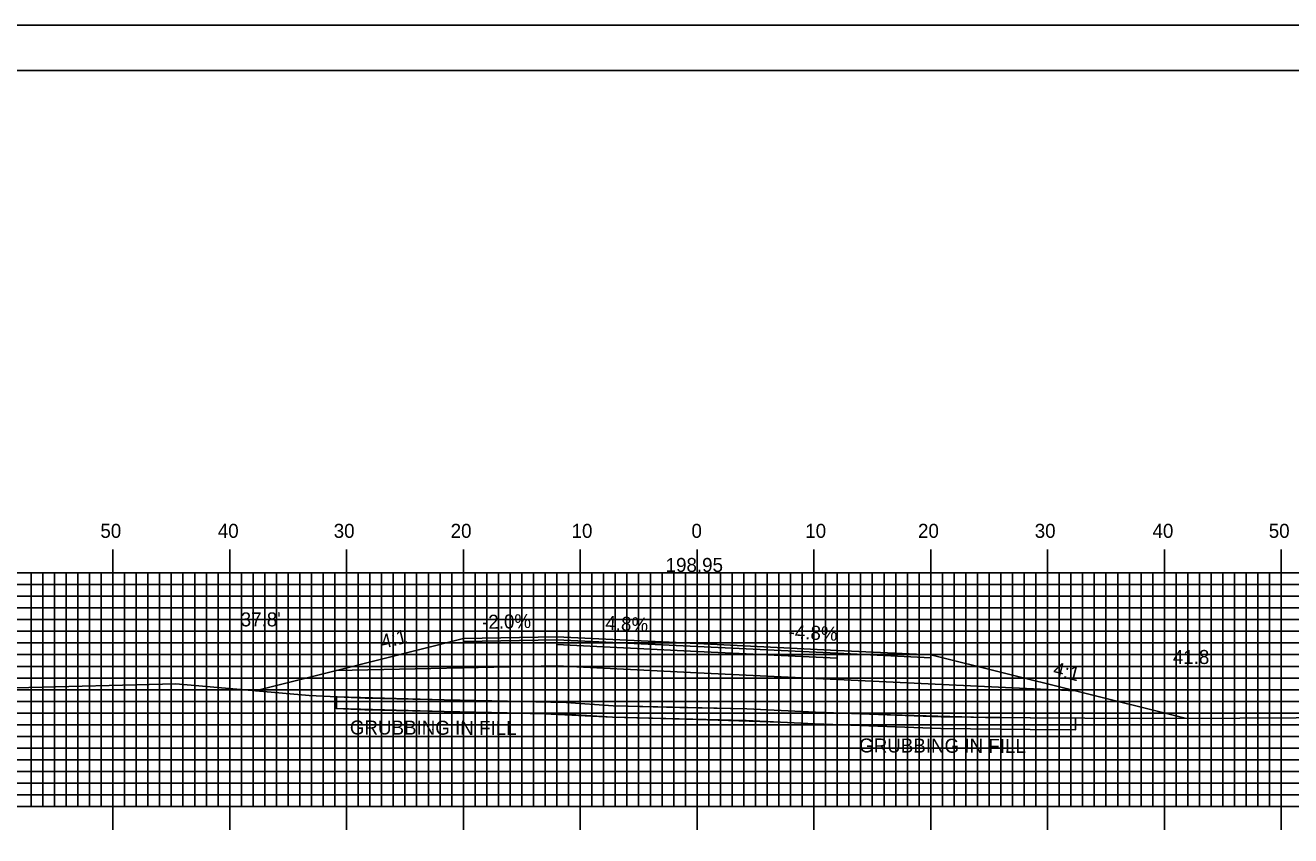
# Model space of a CAD drawing. Extents: x 1814128 to 1814471, y 442591 to 442811.
# Drawn here: x 1814236.5 to 1814344.8, y 442741.2 to 442810.5 of the extents above; entities that cross this region are included whole.
import ezdxf

# ---------------------------------------------------------------- set-up
doc = ezdxf.new("R2010")
doc.units = 0
for name, color, linetype in [('ANNOTATION', 7, 'Continuous'), ('BORDER', 7, 'Continuous'), ('D_Roadway_Centerline', 7, 'Continuous'), ('D_Roadway_Centerline_Text', 7, 'Continuous'), ('D_Roadway_Edge_Shoulder', 7, 'Continuous'), ('D_Roadway_Edge_TW', 7, 'Continuous'), ('D_Roadway_Pavement', 7, 'Continuous'), ('D_Roadway_SlopeLines', 7, 'Continuous'), ('D_Roadway_SubGrade', 7, 'Continuous'), ('D_Text_Standard', 7, 'Continuous'), ('GRUBBING IN FILL', 7, 'Continuous'), ('H_V ANNOTATION', 7, 'Continuous'), ('MAJOR', 7, 'Continuous'), ('MINOR', 7, 'Continuous'), ('PLOT BOUNDARY', 7, 'Continuous'), ('S_Roadway_Centerline', 7, 'Continuous')]:
    doc.layers.add(name, color=color, linetype=linetype)

msp = doc.modelspace()

# ---------------------------------------------------------------- linework, layer by layer
at = {"layer": 'BORDER'}
msp.add_lwpolyline([(1814144.39, 442596.67), (1814464.39, 442596.67), (1814464.39, 442806.67), (1814144.39, 442806.67)], close=True, dxfattribs=at)
at = {"layer": 'D_Roadway_Centerline'}
msp.add_lwpolyline([(1814256.17, 442753.58), (1814261.99, 442755.04), (1814263.12, 442755.32), (1814273.99, 442758.04), (1814281.99, 442758.2), (1814293.99, 442757.62), (1814305.99, 442757.04), (1814313.99, 442756.66), (1814326.37, 442753.57), (1814335.77, 442751.22)], dxfattribs=at)
at = {"layer": 'D_Roadway_Edge_Shoulder'}
for points in [[(1814281.99, 442758.2), (1814273.99, 442758.04), (1814273.99, 442757.79), (1814281.99, 442757.95)], [(1814305.99, 442757.04), (1814313.99, 442756.66), (1814313.99, 442756.41), (1814305.99, 442756.79)]]:
    msp.add_lwpolyline(points, close=True, dxfattribs=at)
at = {"layer": 'D_Roadway_Edge_TW'}
msp.add_lwpolyline([(1814281.99, 442757.95), (1814281.99, 442758.2), (1814293.99, 442757.62), (1814305.99, 442757.04), (1814305.99, 442756.79), (1814293.99, 442757.37)], close=True, dxfattribs=at)
at = {"layer": 'D_Roadway_Pavement'}
msp.add_lwpolyline([(1814281.99, 442757.53), (1814281.99, 442757.95), (1814293.99, 442757.37), (1814305.99, 442756.79), (1814305.99, 442756.38), (1814293.99, 442756.95)], close=True, dxfattribs=at)
at = {"layer": 'D_Roadway_SlopeLines'}
for points in [[(1814273.99, 442758.04), (1814263.12, 442755.32), (1814261.99, 442755.04), (1814256.17, 442753.58)], [(1814313.99, 442756.66), (1814326.37, 442753.57), (1814335.77, 442751.22)]]:
    msp.add_lwpolyline(points, dxfattribs=at)
at = {"layer": 'D_Roadway_SubGrade'}
msp.add_lwpolyline([(1814281.99, 442755.7), (1814263.12, 442755.32), (1814273.99, 442758.04), (1814273.99, 442757.79), (1814281.99, 442757.95), (1814293.99, 442757.37), (1814305.99, 442756.79), (1814313.99, 442756.41), (1814313.99, 442756.66), (1814326.37, 442753.57), (1814305.99, 442754.54), (1814293.99, 442755.12)], close=True, dxfattribs=at)
at = {"layer": 'GRUBBING IN FILL'}
for p, q in [((1814263.12, 442753.07), (1814263.12, 442752.06)), ((1814263.12, 442753.07), (1814263.12, 442752.06)), ((1814326.37, 442751.23), (1814326.37, 442750.23)), ((1814326.37, 442751.23), (1814326.37, 442750.23))]:
    msp.add_line(p, q, dxfattribs=at)
for points in [[(1814263.12, 442753.07), (1814272.35, 442752.8), (1814282.78, 442752.57), (1814286.8, 442752.3), (1814292.52, 442752.16), (1814293.99, 442752.13), (1814293.99, 442751.13), (1814286.76, 442751.31), (1814280.92, 442751.61), (1814272.33, 442751.8), (1814263.12, 442752.06)], [(1814263.12, 442753.07), (1814272.35, 442752.8), (1814282.78, 442752.57), (1814286.8, 442752.3), (1814292.52, 442752.16), (1814293.99, 442752.13), (1814293.99, 442751.13), (1814286.76, 442751.31), (1814280.92, 442751.61), (1814272.33, 442751.8), (1814263.12, 442752.06)], [(1814293.99, 442752.13), (1814298.24, 442752.02), (1814304.13, 442751.76), (1814309.51, 442751.55), (1814318.69, 442751.3), (1814326.37, 442751.23), (1814326.37, 442750.23), (1814322.49, 442750.25), (1814314.86, 442750.35), (1814309.47, 442750.56), (1814304.08, 442750.76), (1814301.14, 442750.89), (1814293.99, 442751.13)], [(1814293.99, 442752.13), (1814298.24, 442752.02), (1814304.13, 442751.76), (1814309.51, 442751.55), (1814318.69, 442751.3), (1814326.37, 442751.23), (1814326.37, 442750.23), (1814322.49, 442750.25), (1814314.86, 442750.35), (1814309.47, 442750.56), (1814304.08, 442750.76), (1814301.14, 442750.89), (1814293.99, 442751.13)]]:
    msp.add_lwpolyline(points, close=True, dxfattribs=at)
msp.add_lwpolyline([(1814263.12, 442752.06), (1814265.55, 442751.95), (1814279.1, 442751.65), (1814282.74, 442751.57), (1814286.76, 442751.31), (1814298.2, 442751.02), (1814304.08, 442750.76), (1814314.86, 442750.35), (1814322.49, 442750.25), (1814326.37, 442750.23)], dxfattribs=at)
msp.add_lwpolyline([(1814263.12, 442752.06), (1814265.55, 442751.95), (1814279.1, 442751.65), (1814282.74, 442751.57), (1814286.76, 442751.31), (1814298.2, 442751.02), (1814304.08, 442750.76), (1814314.86, 442750.35), (1814322.49, 442750.25), (1814326.37, 442750.23)], dxfattribs=at)
at = {"layer": 'MAJOR'}
for p, q in [((1814243.99, 442765.67), (1814243.99, 442763.67)), ((1814253.99, 442765.67), (1814253.99, 442763.67)), ((1814263.99, 442765.67), (1814263.99, 442763.67)), ((1814273.99, 442765.67), (1814273.99, 442763.67)), ((1814283.99, 442765.67), (1814283.99, 442763.67)), ((1814293.99, 442765.67), (1814293.99, 442763.67)), ((1814303.99, 442765.67), (1814303.99, 442763.67)), ((1814313.99, 442765.67), (1814313.99, 442763.67)), ((1814323.99, 442765.67), (1814323.99, 442763.67)), ((1814333.99, 442765.67), (1814333.99, 442763.67)), ((1814343.99, 442765.67), (1814343.99, 442763.67)), ((1814153.99, 442763.67), (1814433.99, 442763.67)), ((1814153.99, 442763.67), (1814433.99, 442763.67)), ((1814243.99, 442743.67), (1814243.99, 442763.67)), ((1814253.99, 442743.67), (1814253.99, 442763.67)), ((1814263.99, 442743.67), (1814263.99, 442763.67)), ((1814273.99, 442743.67), (1814273.99, 442763.67)), ((1814283.99, 442743.67), (1814283.99, 442763.67)), ((1814293.99, 442743.67), (1814293.99, 442763.67)), ((1814303.99, 442743.67), (1814303.99, 442763.67)), ((1814313.99, 442743.67), (1814313.99, 442763.67)), ((1814323.99, 442743.67), (1814323.99, 442763.67)), ((1814333.99, 442743.67), (1814333.99, 442763.67)), ((1814343.99, 442743.67), (1814343.99, 442763.67)), ((1814153.99, 442758.67), (1814433.99, 442758.67)), ((1814153.99, 442753.67), (1814433.99, 442753.67)), ((1814153.99, 442748.67), (1814433.99, 442748.67)), ((1814153.99, 442743.67), (1814433.99, 442743.67)), ((1814153.99, 442743.67), (1814433.99, 442743.67)), ((1814243.99, 442741.66), (1814243.99, 442743.67)), ((1814253.99, 442741.66), (1814253.99, 442743.67)), ((1814263.99, 442741.66), (1814263.99, 442743.67)), ((1814273.99, 442741.66), (1814273.99, 442743.67)), ((1814283.99, 442741.66), (1814283.99, 442743.67)), ((1814293.99, 442741.66), (1814293.99, 442743.67)), ((1814303.99, 442741.66), (1814303.99, 442743.67)), ((1814313.99, 442741.66), (1814313.99, 442743.67)), ((1814323.99, 442741.66), (1814323.99, 442743.67)), ((1814333.99, 442741.66), (1814333.99, 442743.67)), ((1814343.99, 442741.66), (1814343.99, 442743.67))]:
    msp.add_line(p, q, dxfattribs=at)
at = {"layer": 'MINOR'}
for p, q in [((1814236.99, 442743.67), (1814236.99, 442763.67)), ((1814237.99, 442743.67), (1814237.99, 442763.67)), ((1814238.99, 442743.67), (1814238.99, 442763.67)), ((1814239.99, 442743.67), (1814239.99, 442763.67)), ((1814240.99, 442743.67), (1814240.99, 442763.67)), ((1814241.99, 442743.67), (1814241.99, 442763.67)), ((1814242.99, 442743.67), (1814242.99, 442763.67)), ((1814244.99, 442743.67), (1814244.99, 442763.67)), ((1814245.99, 442743.67), (1814245.99, 442763.67)), ((1814246.99, 442743.67), (1814246.99, 442763.67)), ((1814247.99, 442743.67), (1814247.99, 442763.67)), ((1814248.99, 442743.67), (1814248.99, 442763.67)), ((1814249.99, 442743.67), (1814249.99, 442763.67)), ((1814250.99, 442743.67), (1814250.99, 442763.67)), ((1814251.99, 442743.67), (1814251.99, 442763.67)), ((1814252.99, 442743.67), (1814252.99, 442763.67)), ((1814254.99, 442743.67), (1814254.99, 442763.67)), ((1814255.99, 442743.67), (1814255.99, 442763.67)), ((1814256.99, 442743.67), (1814256.99, 442763.67)), ((1814257.99, 442743.67), (1814257.99, 442763.67)), ((1814258.99, 442743.67), (1814258.99, 442763.67)), ((1814259.99, 442743.67), (1814259.99, 442763.67)), ((1814260.99, 442743.67), (1814260.99, 442763.67)), ((1814261.99, 442743.67), (1814261.99, 442763.67)), ((1814262.99, 442743.67), (1814262.99, 442763.67)), ((1814264.99, 442743.67), (1814264.99, 442763.67)), ((1814265.99, 442743.67), (1814265.99, 442763.67)), ((1814266.99, 442743.67), (1814266.99, 442763.67)), ((1814267.99, 442743.67), (1814267.99, 442763.67)), ((1814268.99, 442743.67), (1814268.99, 442763.67)), ((1814269.99, 442743.67), (1814269.99, 442763.67)), ((1814270.99, 442743.67), (1814270.99, 442763.67)), ((1814271.99, 442743.67), (1814271.99, 442763.67)), ((1814272.99, 442743.67), (1814272.99, 442763.67)), ((1814274.99, 442743.67), (1814274.99, 442763.67)), ((1814275.99, 442743.67), (1814275.99, 442763.67)), ((1814276.99, 442743.67), (1814276.99, 442763.67)), ((1814277.99, 442743.67), (1814277.99, 442763.67)), ((1814278.99, 442743.67), (1814278.99, 442763.67)), ((1814279.99, 442743.67), (1814279.99, 442763.67)), ((1814280.99, 442743.67), (1814280.99, 442763.67)), ((1814281.99, 442743.67), (1814281.99, 442763.67)), ((1814282.99, 442743.67), (1814282.99, 442763.67)), ((1814284.99, 442743.67), (1814284.99, 442763.67)), ((1814285.99, 442743.67), (1814285.99, 442763.67)), ((1814286.99, 442743.67), (1814286.99, 442763.67)), ((1814287.99, 442743.67), (1814287.99, 442763.67)), ((1814288.99, 442743.67), (1814288.99, 442763.67)), ((1814289.99, 442743.67), (1814289.99, 442763.67)), ((1814290.99, 442743.67), (1814290.99, 442763.67)), ((1814291.99, 442743.67), (1814291.99, 442763.67)), ((1814292.99, 442743.67), (1814292.99, 442763.67)), ((1814294.99, 442743.67), (1814294.99, 442763.67)), ((1814295.99, 442743.67), (1814295.99, 442763.67)), ((1814296.99, 442743.67), (1814296.99, 442763.67)), ((1814297.99, 442743.67), (1814297.99, 442763.67)), ((1814298.99, 442743.67), (1814298.99, 442763.67)), ((1814299.99, 442743.67), (1814299.99, 442763.67)), ((1814300.99, 442743.67), (1814300.99, 442763.67)), ((1814301.99, 442743.67), (1814301.99, 442763.67)), ((1814302.99, 442743.67), (1814302.99, 442763.67)), ((1814304.99, 442743.67), (1814304.99, 442763.67)), ((1814305.99, 442743.67), (1814305.99, 442763.67)), ((1814306.99, 442743.67), (1814306.99, 442763.67)), ((1814307.99, 442743.67), (1814307.99, 442763.67)), ((1814308.99, 442743.67), (1814308.99, 442763.67)), ((1814309.99, 442743.67), (1814309.99, 442763.67)), ((1814310.99, 442743.67), (1814310.99, 442763.67)), ((1814311.99, 442743.67), (1814311.99, 442763.67)), ((1814312.99, 442743.67), (1814312.99, 442763.67)), ((1814314.99, 442743.67), (1814314.99, 442763.67)), ((1814315.99, 442743.67), (1814315.99, 442763.67)), ((1814316.99, 442743.67), (1814316.99, 442763.67)), ((1814317.99, 442743.67), (1814317.99, 442763.67)), ((1814318.99, 442743.67), (1814318.99, 442763.67)), ((1814319.99, 442743.67), (1814319.99, 442763.67)), ((1814320.99, 442743.67), (1814320.99, 442763.67)), ((1814321.99, 442743.67), (1814321.99, 442763.67)), ((1814322.99, 442743.67), (1814322.99, 442763.67)), ((1814324.99, 442743.67), (1814324.99, 442763.67)), ((1814325.99, 442743.67), (1814325.99, 442763.67)), ((1814326.99, 442743.67), (1814326.99, 442763.67)), ((1814327.99, 442743.67), (1814327.99, 442763.67)), ((1814328.99, 442743.67), (1814328.99, 442763.67)), ((1814329.99, 442743.67), (1814329.99, 442763.67)), ((1814330.99, 442743.67), (1814330.99, 442763.67)), ((1814331.99, 442743.67), (1814331.99, 442763.67)), ((1814332.99, 442743.67), (1814332.99, 442763.67)), ((1814334.99, 442743.67), (1814334.99, 442763.67)), ((1814335.99, 442743.67), (1814335.99, 442763.67)), ((1814336.99, 442743.67), (1814336.99, 442763.67)), ((1814337.99, 442743.67), (1814337.99, 442763.67)), ((1814338.99, 442743.67), (1814338.99, 442763.67)), ((1814339.99, 442743.67), (1814339.99, 442763.67)), ((1814340.99, 442743.67), (1814340.99, 442763.67)), ((1814341.99, 442743.67), (1814341.99, 442763.67)), ((1814342.99, 442743.67), (1814342.99, 442763.67)), ((1814153.99, 442762.67), (1814433.99, 442762.67)), ((1814153.99, 442761.67), (1814433.99, 442761.67)), ((1814153.99, 442760.67), (1814433.99, 442760.67)), ((1814153.99, 442759.67), (1814433.99, 442759.67)), ((1814153.99, 442757.67), (1814433.99, 442757.67)), ((1814153.99, 442756.67), (1814433.99, 442756.67)), ((1814153.99, 442755.67), (1814433.99, 442755.67)), ((1814153.99, 442754.67), (1814433.99, 442754.67)), ((1814153.99, 442752.67), (1814433.99, 442752.67)), ((1814153.99, 442751.67), (1814433.99, 442751.67)), ((1814153.99, 442750.67), (1814433.99, 442750.67)), ((1814153.99, 442749.67), (1814433.99, 442749.67)), ((1814153.99, 442747.67), (1814433.99, 442747.67)), ((1814153.99, 442746.67), (1814433.99, 442746.67)), ((1814153.99, 442745.67), (1814433.99, 442745.67)), ((1814153.99, 442744.67), (1814433.99, 442744.67))]:
    msp.add_line(p, q, dxfattribs=at)
at = {"layer": 'PLOT BOUNDARY'}
msp.add_lwpolyline([(1814128.21, 442590.55), (1814468.21, 442590.55), (1814468.21, 442810.55), (1814128.21, 442810.55)], close=True, dxfattribs=at)
at = {"layer": 'S_Roadway_Centerline'}
msp.add_lwpolyline([(1814235.66, 442753.82), (1814249.38, 442754.17), (1814260.78, 442753.18), (1814265.58, 442752.95), (1814279.13, 442752.65), (1814282.78, 442752.57), (1814286.8, 442752.3), (1814298.24, 442752.02), (1814304.13, 442751.76), (1814314.89, 442751.35), (1814322.5, 442751.25), (1814331.85, 442751.21), (1814340.44, 442751.22), (1814354.92, 442751.33)], dxfattribs=at)

# ---------------------------------------------------------------- texts
at = {"layer": 'ANNOTATION'}
for s, rotation, p in [('-2.0%', 1.1458, (1814275.6, 442758.87)), ('4.8%', 357.2519, (1814286.12, 442758.8)), ('-4.8%', 357.2519, (1814301.8, 442758.05)), ('4:1', 14.0362, (1814267.1, 442757.17)), ('4:1', 345.9638, (1814324.39, 442754.92))]:
    msp.add_text(s, height=1.2, rotation=rotation, dxfattribs=at).set_placement(p)
at = {"layer": 'D_Roadway_Centerline'}
for s, p in [('C', (1814293.99, 442757.62)), ('L', (1814293.99, 442757.61))]:
    msp.add_text(s, height=0.0146, dxfattribs=at).set_placement(p)
at = {"layer": 'D_Roadway_Centerline_Text'}
msp.add_text('198.95', height=1.2, dxfattribs=at).set_placement((1814291.3, 442763.75))
at = {"layer": 'D_Text_Standard'}
for s, p in [("37.8'", (1814254.93, 442759.09)), ("41.8'", (1814334.71, 442755.87))]:
    msp.add_text(s, height=1.2, dxfattribs=at).set_placement(p)
at = {"layer": 'GRUBBING IN FILL'}
for p in [(1814264.27, 442749.84), (1814307.86, 442748.3)]:
    msp.add_text('GRUBBING IN FILL', height=1.2, rotation=359.8053, dxfattribs=at).set_placement(p)
at = {"layer": 'H_V ANNOTATION'}
for s, p in [('50', (1814242.92, 442766.67)), ('40', (1814252.97, 442766.67)), ('30', (1814262.89, 442766.67)), ('20', (1814272.9, 442766.67)), ('10', (1814283.25, 442766.67)), ('0', (1814293.51, 442766.67)), ('10', (1814303.25, 442766.67)), ('20', (1814312.9, 442766.67)), ('30', (1814322.89, 442766.67)), ('40', (1814332.97, 442766.67)), ('50', (1814342.92, 442766.67))]:
    msp.add_text(s, height=1.2, dxfattribs=at).set_placement(p)

doc.saveas('drawing.dxf')
